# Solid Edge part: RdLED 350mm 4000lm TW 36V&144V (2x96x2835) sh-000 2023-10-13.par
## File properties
Author: jaroslaw.przewlocki
Template: iso metric part.par
Last saved by: jaroslaw.przewlocki
Revision: 1
Application: Solid Edge
Gęstość: 0,000 kg/m^3
Dokładność: 0,990
Username: jaroslaw.przewlocki
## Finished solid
Body 1: solid body, 3991 faces, 10408 edges, 6852 vertices.
  Faces by surface: plane 3468, cylinder 259, torus 104, cone 88, spline 52, sphere 20
  Edges by curve: line 9164, curve on surface 654, circle 300, spline 158, ellipse 132
Bounding box of the edges (mm; curved faces can reach further): 350.000 x 350.000 x 4.450, from (-175, -175, 0) to (175, 175, 4.45).
Cylindrical faces by radius (mm): R0.199 x2, R0.2 x78, R0.2002 x4, R0.2169 x6, R0.25 x24, R0.3 x4, R0.3373 x6, R0.4 x16, R0.4006 x4, R0.4008 x4, R0.525 x4, R0.6 x24, R1 x14, R1.0894 x4, R1.0991 x8, R1.1 x28, R2.1237 x2, R2.15 x26, R175 x1
Conical faces (half-angle, radius in mm at the cone's reference point): 0.3913 deg R1.0968 x4, 0.447 deg R1.0952 x4, 0.464 deg R1.0955 x4, 0.5 deg R0.5056 x8, 0.5 deg R1.0082 x8, 1 deg R0.5511 x4, 10 deg R0.2132 x4, 10 deg R0.4132 x4, 15.6748 deg R1.1041 x2, 15.6751 deg R1.1041 x2, 15.7937 deg R1.1267 x2, 15.7938 deg R1.1267 x2, 18.4844 deg R1.0657 x8, 18.9316 deg R0.5099 x4, 19.4337 deg R0.5111 x4, 27.363 deg R0.6214 x4, 40.1968 deg R0.519 x2, 40.228 deg R0.5176 x2, 42.9179 deg R0.4919 x2, 42.9331 deg R0.4916 x2, 45 deg R0.575 x4, 45 deg R0.625 x8
Toroidal faces (ring radius, tube radius in mm): R0.0958 r0.3997 x8, R0.1 r0.2 x2, R0.1075 r0.4 x4, R0.1101 r0.4001 x4, R0.1216 r0.4 x4, R0.1234 r0.4 x4, R0.1634 r0.2287 x2, R0.1641 r0.2287 x2, R0.3286 r0.2001 x2, R0.3702 r0.4 x4, R0.3818 r0.2 x4, R0.4163 r0.3984 x4, R0.4824 r0.2001 x2, R0.4952 r0.2 x2, R0.6008 r0.3968 x4, R0.6009 r0.3969 x4, R0.6227 r0.2 x2, R0.6235 r0.2 x2, R0.8 r0.2 x8, R0.8522 r0.3 x4, R0.9002 r0.2 x2, R0.9018 r0.2 x2, R0.9181 r0.2227 x4, R0.9197 r0.223 x2, R0.9199 r0.223 x2, R0.9663 r0.2263 x2, R0.9665 r0.2263 x2, R1.3 r0.2 x4, R1.327 r1.1 x4, R1.3271 r1.1 x4, R1.8741 r0.2175 x2, R1.8987 r0.2 x2
Spherical faces by radius (mm): R0.2 x16, R0.6 x4
Planar faces by outward normal: +x 68, +y 68, +z 627, -x 68, -y 86, -z 15, oblique 2536
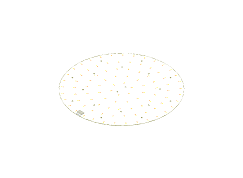
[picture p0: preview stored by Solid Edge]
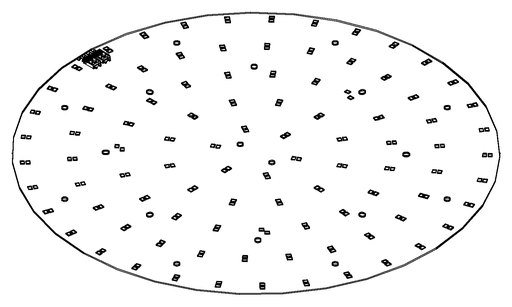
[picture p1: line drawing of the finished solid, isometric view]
